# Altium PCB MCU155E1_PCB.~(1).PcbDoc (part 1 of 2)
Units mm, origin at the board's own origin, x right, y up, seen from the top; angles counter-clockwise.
Board outline 32 x 29 mm, 4 copper layers (Top Layer, Layer 1, Layer 2, Bottom Layer), stack 1.567 mm thick; 102 components, 61 nets, 283 pads, 120 vias.
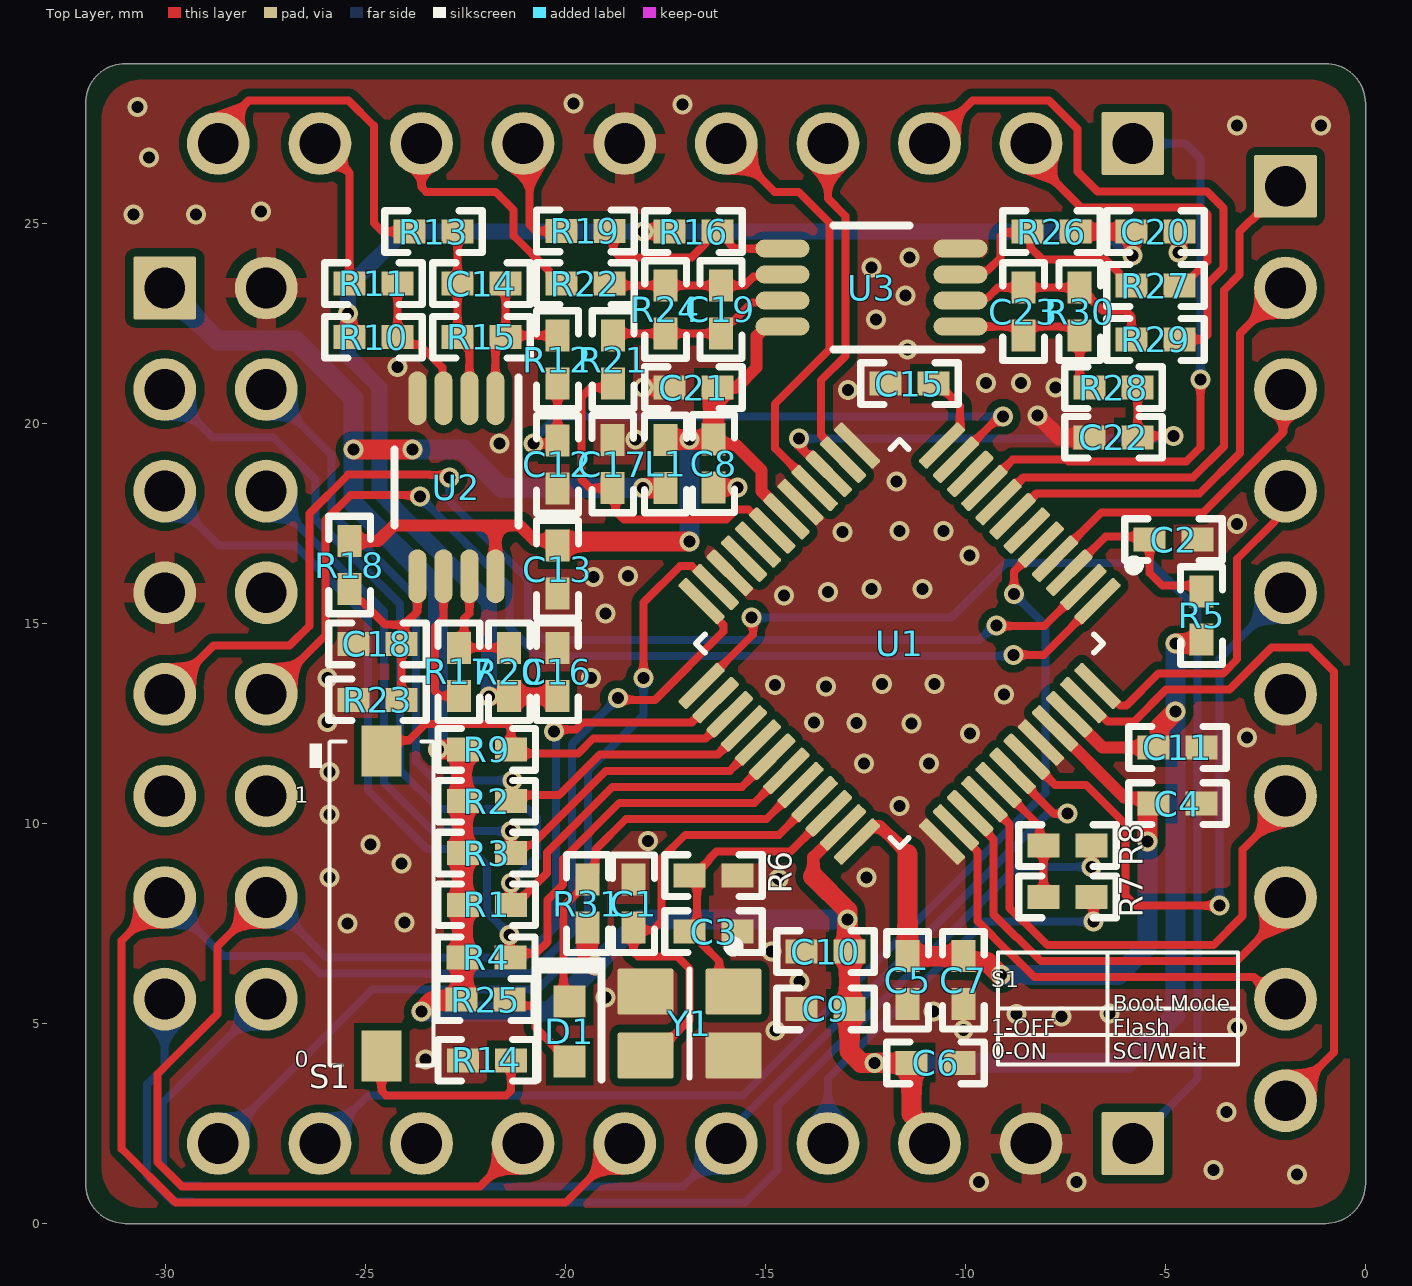
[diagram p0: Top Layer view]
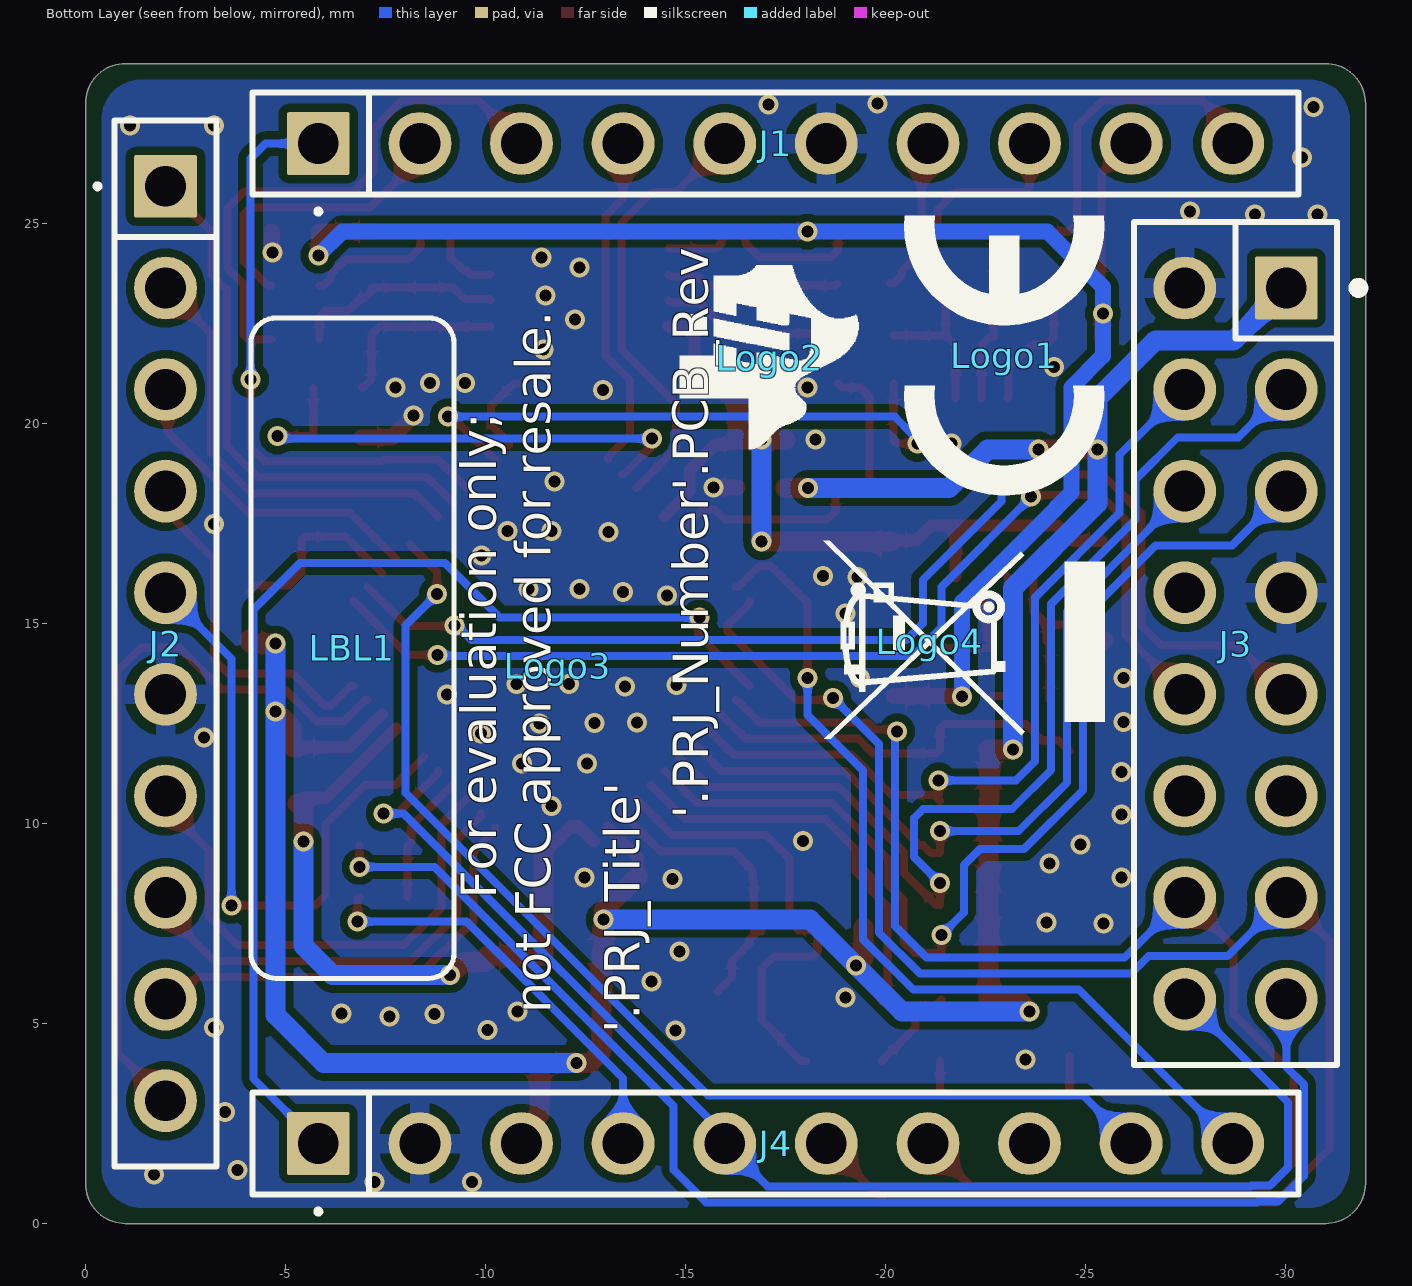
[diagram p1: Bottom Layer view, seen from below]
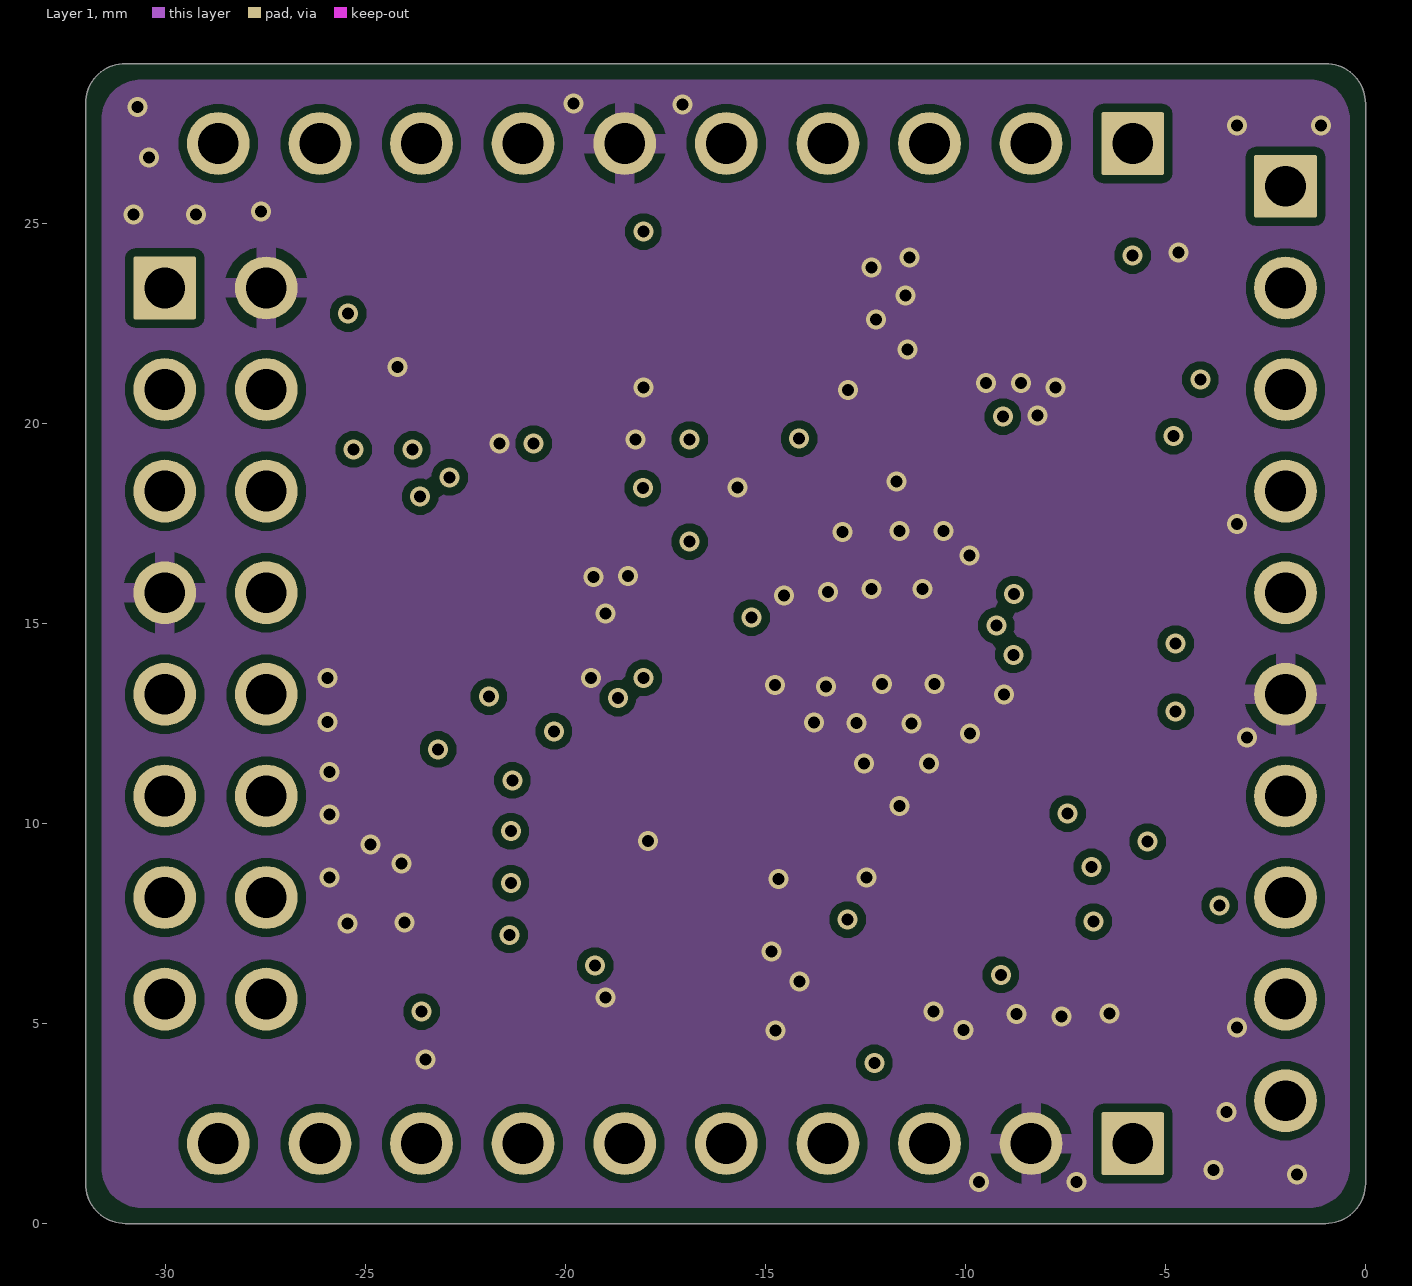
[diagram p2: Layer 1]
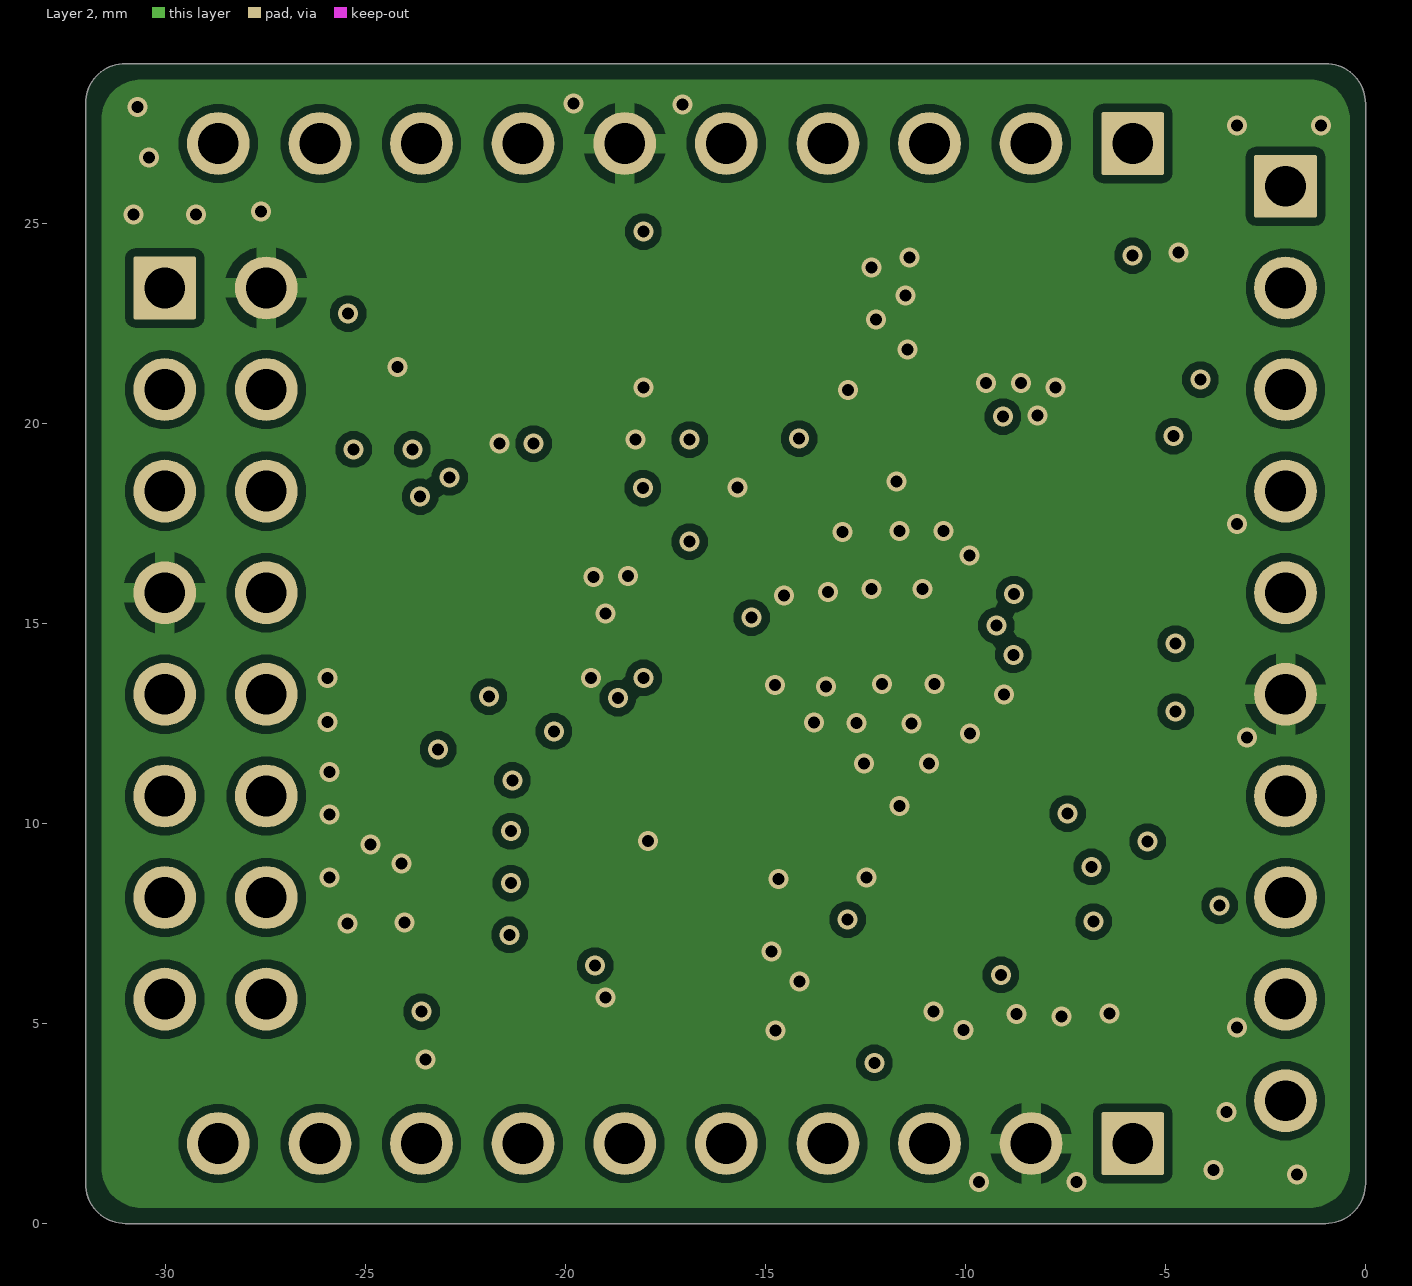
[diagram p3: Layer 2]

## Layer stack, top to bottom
Top Solder: solder mask 0.0102, Solder Resist, Dk 3.5
Top Layer: signal copper 0.035
Dielectric 1: prepreg 0.2184, PP-023, Dk 4.5
Layer 1: signal copper 0.035
Dielectric1: core 0.9906, Core-042, Dk 4.6
Layer 2: signal copper 0.035
Dielectric 2: prepreg 0.2184, PP-023, Dk 4.5
Bottom Layer: signal copper 0.035
Bottom Solder: solder mask 0.0102, Solder Resist, Dk 3.5

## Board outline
-32,1 -32,28 cw(c-31,28) -31,29 -1,29 cw(c-1,28) 0,28 0,1 cw(c-1,1) -1,0 -31,0 cw(c-31,1)

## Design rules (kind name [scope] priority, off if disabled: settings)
AcuteAngle [All] p1: minimum=4.50000000000000E+0001 checktracksonly=FALSE
AssemblyTestPointUsage [All] p1: valid=2
BoardOutlineClearance BoardOutlineClearance_MountingHoles [OnCopper and InComponentClass('Mounting Holes')] p1: gap=0 ignorepadtopadclearanceinfootprint=FALSE
BoardOutlineClearance BoardOutlineClearance_Poly [OnCopper and IsPoly] p2: gap=0 ignorepadtopadclearanceinfootprint=FALSE
BoardOutlineClearance [OnCopper and Not InComponentClass('Logo') and not InComponentClass('FiducialMark') and not InRegion(1000,500,4000,800) and not InPoly] p3: gap=0 ignorepadtopadclearanceinfootprint=FALSE
Clearance Clearance_1 [(InComponent('J1') or InComponent('J2') or InComponent('J3') or InComponent('J4') ) and not HasFootprint('fiducial10-20')] p1: gap=0.19 ignorepadtopadclearanceinfootprint=TRUE
Clearance PB+ToPB- [InNetClass('HV') vs InNetClass('LV_Signal')] p2: gap=3 ignorepadtopadclearanceinfootprint=TRUE
Clearance PB-ToACN [InNetClass('LV Signal') vs InNetClass('ACN')] p3: gap=3 ignorepadtopadclearanceinfootprint=TRUE
Clearance ACLToACN [InNetClass('ACL') vs InNetClass('ACN')] p4: gap=2 ignorepadtopadclearanceinfootprint=FALSE
Clearance ISOToAll [InNetClass('Isolation') vs not InNetClass('Isolation')   and (not  OnLayer('Keep-Out Layer'))] p5: gap=6 ignorepadtopadclearanceinfootprint=TRUE
Clearance PB-ToACL [InNetClass('LV Signal') vs InNetClass('ACL')] p6: gap=3 ignorepadtopadclearanceinfootprint=TRUE
Clearance PB+ToACL [InNetClass('V_BUS') vs InNetClass('ACL')] p7: gap=3 ignorepadtopadclearanceinfootprint=TRUE
Clearance PB+ToACN [InNetClass('V_BUS') vs InNetClass('ACN')] p8: gap=1.5 ignorepadtopadclearanceinfootprint=TRUE
Clearance SMTPadToTHHole [not IsVia and OnLayer('Multi-Layer') and not InComponent('J1') and not InComponent('J2') and not InComponent('J3') and not InComponent('J4') and not InComponent('J12') and PadIsPlated vs InSMTComponent and OnLayer('Bottom Layer') and not HasFootprint('TP_SM_1MM')] p9: gap=0.15 ignorepadtopadclearanceinfootprint=FALSE except(3: SMDPad-THPad)
Clearance [All vs not HasFootprint('fiducial10-20') or (InComponent('J1') or InComponent('J2') or InComponent('J3') or InComponent('J4') )] p10: gap=0.2 ignorepadtopadclearanceinfootprint=TRUE
ComponentClearance ComponentClearance_MountingHoles_FiducialMarks [InComponentClass('Mounting Holes') vs InComponentClass('FiducialMark')] p1: gap=1.27 collisioncheckmode=3 verticalgap=0.254 showdistances=FALSE
ComponentClearance ComponentClearance_Shunt [InComponentClass('Header') vs InComponentClass('Shunt')] p2: gap=0 collisioncheckmode=3 verticalgap=0 showdistances=FALSE
ComponentClearance ComponentClearance_Logo [InComponentClass('Logo')] p3: gap=0.762 collisioncheckmode=3 verticalgap=0.254 showdistances=FALSE
ComponentClearance ComponentClearance_ScrewToNut [(HasFootprint('NY PMS 440 0025 PH')) vs (HasFootprint('Keystone_1902C'))] p4: gap=0.127 collisioncheckmode=3 verticalgap=0.254 showdistances=FALSE
ComponentClearance ComponentClearance_MountingHoles [InComponentClass('Mounting Holes')] p5: gap=2.54 collisioncheckmode=3 verticalgap=2540 showdistances=FALSE
ComponentClearance ComponentClearance_SmallPassives [HasFootprint('0201*') or HasFootprint('0402*') or HasFootprint('0508') or HasFootprint('0603*') or HasFootprint('0612') or HasFootprint('0805*') or HasFootprint('0815*') or HasFootprint('0830*') or HasFootprint('1206*') or HasFootprint('1210*') or HasFootprint('1808*') or HasFootprint('1812*') or HasFootprint('1825*') or HasFootprint('2010*') or HasFootprint('2220*') or HasFootprint('2225*') or HasFootprint('2512*') or HasFootprint('2728*') or HasFootprint('3518*') vs HasFootprint('0201*') or HasFootprint('0402*') or HasFootprint('0508') or HasFootprint('0603*') or HasFootprint('0612') or HasFootprint('0805*') or HasFootprint('0815*') or HasFootprint('0830*') or HasFootprint('1206*') or HasFootprint('1210*') or HasFootprint('1808*') or HasFootprint('1812*') or HasFootprint('1825*') or HasFootprint('2010*') or HasFootprint('2220*') or HasFootprint('2225*') or HasFootprint('2512*') or HasFootprint('2728*') or HasFootprint('3518*')] p6: gap=0.38 collisioncheckmode=3 verticalgap=0.254 showdistances=FALSE
ComponentClearance ComponentClearance_THtoSMT [IsThruComponent vs IsSMTComponent] p7: gap=0.762 collisioncheckmode=3 verticalgap=0.762 showdistances=FALSE
ComponentClearance ComponentClearance_THtoTH [IsThruComponent vs IsThruComponent] p8: gap=0.508 collisioncheckmode=3 verticalgap=0.762 showdistances=FALSE
ComponentClearance [All] p9: gap=0.508 collisioncheckmode=3 verticalgap=0.254 showdistances=FALSE
DiffPairsRouting [All] p1: maxlimit=2.54 minlimit=0.254 mostfreqgap=0.254 toplayer_minwidth=0.381 toplayer_maxwidth=0.381 toplayer_prefwidth=0.381 midlayer1_minwidth=0.381 midlayer1_maxwidth=0.381 midlayer1_prefwidth=0.381 midlayer2_minwidth=0.381 midlayer2_maxwidth=0.381 midlayer2_prefwidth=0.381 bottomlayer_minwidth=0.381 bottomlayer_maxwidth=0.381 bottomlayer_prefwidth=0.381 maxuncoupledlength=25.4
FabricationTestPointUsage TestPointUsage [All] p1: valid=2 allowmultiple=FALSE
FabricationTestpoint Testpoint [All] p1: side=3 testpointundercomponent=TRUE minsize=1.016 maxsize=2.54 preferedsize=1.524 minholesize=0 maxholesize=1.016 preferedholesize=0.813 testpointgrid=0.025 allowsidetop=TRUE allowsidebottom=TRUE usegrid=TRUE gridtolerance=0
FanoutControl Fanout_LCC [IsLCC] p1: bgadir=Out bgaviamode=Centered fanoutstyle=Auto fanoutdirection=Alternating viagrid=0.025 // Fanout_LCC (Default Rule)
FanoutControl Fanout_BGA [IsBGA] p2: bgadir=Out bgaviamode=Centered fanoutstyle=Auto fanoutdirection=Alternating viagrid=0.025 // Fanout_BGA (Default Rule)
FanoutControl Fanout_Default [All] p4: bgadir=Out bgaviamode=Centered fanoutstyle=Auto fanoutdirection=Alternating viagrid=0.025 // Fanout_Default (Default Rule)
FanoutControl Fanout_Small [(CompPinCount < 5)] p5: bgadir=Out bgaviamode=Centered fanoutstyle=Auto fanoutdirection=OutThenIn viagrid=0.025 // Fanout_Small (Default Rule)
HoleSize [All] p1: absolutevalues=TRUE maxlimit=6.375 minlimit=0.2 maxpercent=80.000 minpercent=20.000
MinimumAnnularRing MinimumAnnularRing_ThermalPadVias [IsVia and InAnyComponent] p1: minimumring=0.15
MinimumAnnularRing [All] p2: minimumring=0.2
MinimumSolderMaskSliver MinimumSolderMaskSliver_Logo [InComponentClass('Logo') vs InComponentClass('Logo')] p1: minsoldermaskwidth=0.018
MinimumSolderMaskSliver [All] p2: minsoldermaskwidth=0.1
PlaneConnect [All] p1: planeconnectstyle=Direct reliefexpansion=0.254 reliefentries=4 reliefconductorwidth=0.254 reliefairgap=0.254
PolygonConnect "Thermal relief" [All vs InNet('GND') or innet('GND_ISO')  or innet('ubus')] p1: thpad.connectstyle=Relief thpad.reliefconductorwidth=0.5 thpad.reliefentries=4 thpad.polygonreliefangle="90 Angle" thpad.airgapwidth=0.254 smdpad.connectstyle=Direct smdpad.reliefconductorwidth=0.5 smdpad.reliefentries=4 smdpad.polygonreliefangle="90 Angle" smdpad.airgapwidth=0.254 via.connectstyle=Direct via.reliefconductorwidth=0.5 via.reliefentries=4 via.polygonreliefangle="90 Angle" via.airgapwidth=0.254
PolygonConnect [All] p2: connectstyle=Direct reliefconductorwidth=0.254 reliefentries=4 polygonreliefangle="90 Angle" airgapwidth=0.254
RoutingVias ThermalPadVias [IsVia and InAnyComponent] p1: holewidth=0.2 width=0.5 viastyle="Through Hole" minholewidth=0.2 minwidth=0.5 maxholewidth=0.33 maxwidth=0.6
RoutingVias [All] p2: holewidth=0.2 width=0.5 viastyle="Through Hole" minholewidth=0.2 minwidth=0.4 maxholewidth=1 maxwidth=1.4
SilkToBoardRegionClearance [Not ((IsComment or IsDesignator) And (Hide <> 'False')) and not InRegion(1000,500,4000,800)] p1:
SilkToSilkClearance SilkToSilkClearance_Pb-FreeLogo [(HasFootprint('Pb-Free_Overlay_Medium') OR HasFootprint('Pb-Free_Overlay_Small')) vs (HasFootprint('Pb-Free_Overlay_Medium') OR HasFootprint('Pb-Free_Overlay_Small'))] p1: silktosilkclearance=0
SilkToSilkClearance [All] p2: silktosilkclearance=0.1
SilkToSolderMaskClearance SilkToComponentPadClearance [(IsPad or IsFill or IsRegion) and InAnycomponent] p1: minsilkscreentomaskgap=0.127 clearancetoexposedcopper=TRUE
SilkToSolderMaskClearance "Silk to Solder Mask Opening" [All] p2: minsilkscreentomaskgap=0.1 clearancetoexposedcopper=FALSE
SolderMaskExpansion [All] p1: expansion=0.05 istentingtop=FALSE
UnRoutedNet [All] p1: checkbadconnections=TRUE
Width [All] p1: maxlimit=5 minlimit=0.2 preferedwidth=0.3 minimp=50.000000 maximp=50.000000 favimp=50.000000 checkconnectedcopper=TRUE
14 further rules are at their usual default settings.

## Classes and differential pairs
component class Logo: Logo2
component class Label: LBL1
component class TIEVM-MC-MODULE-F280013x: C1 C2 C3 C4 C5 C6 C7 C8 C9 C10 C11 C12 C13 C14 C15 C16 C17 C18 C19 C20 C21 C22 C23 D1 J1 J2 J3 J4 L1 LBL1 Logo1 Logo2 Logo3 Logo4 R1 R2 R3 R4 R5 R6 R7 R8 R9 R10 R11 R12 R13 R14 R15 R16 R17 R18 R19 R20 R21 R22 R23 R24 R25 R26 R27 R28 R29 R30 R31 S1 U1 U2 U3 Y1

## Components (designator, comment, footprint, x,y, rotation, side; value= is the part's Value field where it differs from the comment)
C1 "GRM1555C1H120JA01D" 0402 -18.3,7.998 r270 top value=12pF
C2 "GRM155R71C104KA88D" 0402 -4.8,17.1 r0 top value=0.1uF
C3 "GRM1555C1H120JA01D" 0402 -16.3,7.3 r0 top value=12pF
C4 "GRM155R71C104KA88D" 0402 -4.7,10.5 r180 top value=0.1uF
C5 "GRM155R71C104KA88D" 0402 -11.448,6.083 r90 top value=0.1uF
C6 "GRM155R61A106ME11" 0402 -10.75,4.015 r0 top value=10uF
C7 "GRM155R61A106ME11" 0402 -10.051,6.083 r90 top value=10uF
C8 "GRM155R61A106ME11" 0402 -16.3,19 r270 top value=10uF
C9 "GRM155R61A106ME11" 0402 -13.5,5.366 r180 top value=10uF
C10 "GRM155R71C104KA88D" 0402 -13.5,6.8 r180 top value=0.1uF
C11 "GRM155R71C104KA88D" 0402 -4.7,11.901 r0 top value=0.1uF
C12 "C1005C0G1H221F050BA" 0402 -20.2,18.977 r270 top value=220pF
C13 "GRM155R71C104KA88D" 0402 -20.2,16.353 r270 top value=0.1uF
C14 "GRM1555C1H101JA01D" 0402 -22.1,23.5 r0 top value=100pF
C15 "GRM155R61A225ME95" 0402 -11.4,21 r180 top value=2.2uF
C16 "GRM155R61C103KA01D" 0402 -20.201,13.793 r90 top value=0.01uF
C17 "C1005C0G1H221F050BA" 0402 -18.82,18.988 r90 top value=220pF
C18 "GRM155R71C104KA88D" 0402 -24.701,14.491 r180 top value=0.1uF
C19 "GRM1555C1H101JA01D" 0402 -16.113,22.852 r270 top value=100pF
C20 "GRM155R71C104KA88D" 0402 -5.25,24.8 r0 top value=0.1uF
C21 "GRM155R71C104KA88D" 0402 -16.8,20.9 r180 top value=0.1uF
C22 "C1005C0G1H221F050BA" 0402 -6.3,19.656 r180 top value=220pF
C23 "GRM1555C1H101JA01D" 0402 -8.548,22.8 r270 top value=100pF
D1 "LTST-C193KRKT-5A" LTST-C193_Red -19.9,4.8 r90 top value=Red
J1 "SSQ-110-03-T-S" FP-SSQ-110-03-T-S_CONN_RCPT10-MFG -17.25,27 r180 bottom
J2 "SSQ-110-03-T-S" FP-SSQ-110-03-T-S_CONN_RCPT10-MFG -2,14.5 r270 bottom locked
J3 "SSQ-108-03-T-D" FP-SSQ-108-03-T-D_HDR16-MFG -28.75,14.5 r270 bottom locked
J4 "SSQ-110-03-T-S" FP-SSQ-110-03-T-S_CONN_RCPT10-MFG -17.25,2 r180 bottom locked
L1 "782423100" 0402 -17.5,18.988 r90 top value="10 ohm"
LBL1 "THT-14-423-10" Label_650x200 -6.674,14.385 r270 bottom
Logo1 "CE Mark" CE_Mark_5mm -22.967,21.7 r90 bottom
Logo2 "Texas Instruments" TI_Symbol_Overlay_Small -17.1,21.65 r90 bottom
Logo3 "FCC disclaimer" FCC_disclaimer_stacked -11.8,13.95 r90 bottom
Logo4 "WEEE logo" WEEE_Minimum -21.1,14.55 r90 bottom
M44 "Comment" Arrow 343.55,113.9 r0 top
M45 "Comment" Arrow 386.55,113.9 r180 bottom
M46 "Comment" MARK 416.05,-5.6 r0 top
M47 "Comment" Toolinghole 401.05,-7.1 r0 top
M48 "Comment" "White oil-26X4" 322.05,111.9 r0 top
M49 "Comment" "Bad Mark" 386.05,-5.6 r0 top
M49 "Comment" MARK 411.05,-5.6 r0 top
M49_1 "Comment" "Bad Mark" 354.05,-5.6 r0 top
M49_2 "Comment" "Bad Mark" 322.05,-5.6 r0 top
M50 "Comment" MARK 266.05,-5.6 r0 top
M51 "Comment" MARK 266.05,112.4 r0 top
M52 "Comment" MARK 416.05,112.4 r0 top
M53 "Comment" Toolinghole 276.05,-7.1 r0 top
M54 "Comment" Toolinghole 276.05,113.9 r0 top
M55 "Comment" Toolinghole 406.05,113.9 r0 top
M56 "Comment" "Bad Mark" 381.05,-5.6 r0 top
M56_1 "Comment" "Bad Mark" 349.05,-5.6 r0 top
M56_2 "Comment" "Bad Mark" 317.05,-5.6 r0 top
M57 "Comment" "Bad Mark" 376.05,-5.6 r0 top
M57_1 "Comment" "Bad Mark" 344.05,-5.6 r0 top
M57_2 "Comment" "Bad Mark" 312.05,-5.6 r0 top
M57_2_1 "Comment" "Bad Mark" 302.05,-5.6 r0 top
M57_2_2 "Comment" "Bad Mark" 290.05,-5.6 r0 top
M58 "Comment" "Bad Mark" 371.05,-5.6 r0 top
M58_1 "Comment" "Bad Mark" 339.05,-5.6 r0 top
M58_2 "Comment" "Bad Mark" 307.05,-5.6 r0 top
M58_2_1 "Comment" "Bad Mark" 297.05,-5.6 r0 top
M59 "Comment" "Bad Mark" 366.05,-5.6 r0 top
M59_1 "Comment" "Bad Mark" 334.05,-5.6 r0 top
M60 "Comment" "Bad Mark" 361.05,-5.6 r0 top
M60_1 "Comment" "Bad Mark" 329.05,-5.6 r0 top
M61 "Comment" "Bad Mark" 393.05,-5.6 r0 top
R1 "ERJ-2RKF2401X" 0402 -21.965,7.967 r180 top value=2.40k
R2 "RC0402FR-0710KL" 0402 -21.965,10.557 r180 top value=10.0k
R3 "RC0402FR-0710KL" 0402 -21.965,9.262 r180 top value=10.0k
R4 "RC0402FR-0710KL" 0402 -21.981,6.647 r180 top value=10.0k
R5 "RC0402FR-0710KL" 0402 -4.1,15.2 r270 top value=10.0k
R6 "RG1005P-104-B-T5" 0402 -16.3,8.698 r180 top value=100k
R7 "RC0402JR-070RL" 0402 -7.45,8.165 r180 top value=0
R8 "RC0402JR-070RL" 0402 -7.45,9.45 r180 top value=0
R9 "CMP-0026949-3" 0402 -21.965,11.852 r180 top value=56k
R10 "RC0402FR-0710KL" 0402 -24.8,22.158 r180 top value=10.0k
R11 "ERJ-2RKF2401X" 0402 -24.8,23.5 r0 top value=2.40k
R12 "RC0402FR-07100RL" 0402 -20.2,21.6 r270 top value=100
R13 "ERJ-2RKF2401X" 0402 -23.3,24.8 r0 top value=2.40k
R14 "CMP-0026890-5" 0402 -21.965,4.082 r180 top value=2.2k
R15 "RC0402FR-0710KL" 0402 -22.1,22.158 r0 top value=10.0k
R16 "RC0402FR-0710KL" 0402 -16.8,24.8 r180 top value=10.0k
R17 "RC0402FR-0710KL" 0402 -22.664,13.793 r270 top value=10.0k
R18 "RC0402FR-0710KL" 0402 -25.399,16.463 r90 top value=10.0k
R19 "ERJ-2RKF2401X" 0402 -19.501,24.814 r0 top value=2.40k
R20 "RC0402FR-07100RL" 0402 -21.407,13.793 r270 top value=100
R21 "RC0402FR-07100RL" 0402 -18.811,21.6 r270 top value=100
R22 "ERJ-2RKF2401X" 0402 -19.501,23.5 r0 top value=2.40k
R23 "RC0402FR-0710KL" 0402 -24.7,13.094 r0 top value=10.0k
R24 "RC0402FR-0710KL" 0402 -17.498,22.852 r270 top value=10.0k
R25 "RC0402FR-071KL" 0402 -22,5.6 r0 top value=1.00k
R26 "RC0402FR-0710KL" 0402 -7.85,24.8 r0 top value=10.0k
R27 "ERJ-2RKF2401X" 0402 -5.25,23.451 r180 top value=2.40k
R28 "RC0402FR-07100RL" 0402 -6.3,20.9 r0 top value=100
R29 "ERJ-2RKF2401X" 0402 -5.25,22.101 r180 top value=2.40k
R30 "RC0402FR-0710KL" 0402 -7.146,22.8 r270 top value=10.0k
R31 "CMP-0026949-3" 0402 -19.45,8 r270 top value=56k
S1 "CHS-01TB" SW_CHS-01TB -24.6,8 r0 top
U1 "F2800137PT" PT0048A-MFG -11.65,14.5 r225 top locked
U2 "TLV9062IDGKR" DGK0008A_N -22.727,18.406 r270 top
U3 "TLV9062IDGKR" DGK0008A_N -12.35,23.4 r180 top
Y1 "830108207209" FP-830108207209_SMT_CRYSTAL_3MM2_2MM5-MFG -16.9,5 r180 top

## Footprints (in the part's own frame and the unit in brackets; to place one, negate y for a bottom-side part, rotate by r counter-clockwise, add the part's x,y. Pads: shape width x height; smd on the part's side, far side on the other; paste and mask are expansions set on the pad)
0402 [mm] "0402 from SM-752 data"
  rect 0.8x0.6 smd: 1(-0.6,0) 2(0.6,0)
  silkscreen extent -1.22,-0.52 1.22,0.52, body extent -0.55,-0.3 0.55,0.3, height 0.6
Arrow [mm] "·½Ïò¼ýÍ·"
  silkscreen extent 0,-2 43,2
"Bad Mark" [mm]
  round 2 on Bottom Solder: 2(0,0)
  round 2 on Top Solder: 2(0,0)
  Top Layer pour cut-out: -1.051,0 -0.971,-0.402 -0.743,-0.743 -0.402,-0.971 0,-1.051 0,-1.051 0.402,-0.971 0.743,-0.743 0.971,-0.402 1.051,0 1.051,0 0.971,0.402 0.743,0.743 0.402,0.971 0,1.051 0,1.051 -0.402,0.971 -0.743,0.743 -0.971,0.402 -1.051,0
  Top Layer region: -0.5,-0.25 -0.5,0.25 0.5,0.25 0.5,-0.25
  Top Layer region: -0.25,0.5 0.25,0.5 0.25,-0.5 -0.25,-0.5
  Bottom Layer pour cut-out: 1.051,0 0.971,-0.402 0.743,-0.743 0.402,-0.971 0,-1.051 0,-1.051 -0.402,-0.971 -0.743,-0.743 -0.971,-0.402 -1.051,0 -1.051,0 -0.971,0.402 -0.743,0.743 -0.402,0.971 0,1.051 0,1.051 0.402,0.971 0.743,0.743 0.971,0.402 1.051,0
  Bottom Layer region: 0.25,0.5 -0.25,0.5 -0.25,-0.5 0.25,-0.5
  Bottom Layer region: 0.5,-0.25 0.5,0.25 -0.5,0.25 -0.5,-0.25
CE_Mark_5mm [mm] "Minimum text height for CE Mark"
  silkscreen extent -3.5,-2.5 3.5,2.5
DGK0008A_N [mm] "TSOP, 8-Leads, Body 3x3mm, Pitch 0.65mm, IPC Medium Density"
  oval 1.35x0.45 smd: 1(-2.225,0.975) 2(-2.225,0.325) 3(-2.225,-0.325) 4(-2.225,-0.975) 5(2.225,-0.975) 6(2.225,-0.325) 7(2.225,0.325) 8(2.225,0.975)
  silkscreen extent -2.75,-1.55 0.95,1.55, body extent -2.45,-1.5 2.45,1.5, height 0.96
FCC_disclaimer_stacked [mm]
FP-830108207209_SMT_CRYSTAL_3MM2_2MM5-MFG [mm]
  rrect9% 1.4x1.15 smd paste+0 mask+0: 1(-1.1,-0.8) 2(1.1,-0.8) 3(1.1,0.8) 4(-1.1,0.8)
  silkscreen extent -1.23,-2.05 0,1.35, body extent -1.9,-1.47 1.9,1.48, height 0.25
FP-SSQ-108-03-T-D_HDR16-MFG [mm]
  rrect6% 1.57x1.57 hole 1.02 paste+0 mask+0: 1(-8.89,1.27)
  round 1.57 hole 1.02 paste+0 mask+0: 2(-8.89,-1.27) 3(-6.35,1.27) 4(-6.35,-1.27) 5(-3.81,1.27) 6(-3.81,-1.27) 7(-1.27,1.27) 8(-1.27,-1.27) 9(1.27,1.27) 10(1.27,-1.27) 11(3.81,1.27) 12(3.81,-1.27) 13(6.35,1.27) 14(6.35,-1.27) 15(8.89,1.27) 16(8.89,-1.27)
  silkscreen extent -10.54,-2.54 10.54,3.19, body extent -10.42,-2.48 10.42,2.48, height 8.64
FP-SSQ-110-03-T-S_CONN_RCPT10-MFG [mm]
  rrect6% 1.57x1.57 hole 1.02 paste+0 mask+0: 1(-11.43,0)
  round 1.57 hole 1.02 paste+0 mask+0: 2(-8.89,0) 3(-6.35,0) 4(-3.81,0) 5(-1.27,0) 6(1.27,0) 7(3.81,0) 8(6.35,0) 9(8.89,0) 10(11.43,0)
  silkscreen extent -13.08,-1.76 13.08,1.27, body extent -12.95,-1.21 12.95,1.21, height 8.64
Label_650x200 [mil] "Thermal Transfer Label"
  round 1 on Mech14: 0(0,0)
  silkscreen extent -325,-100 325,100, body extent -325,-100 325,100, height 1
LTST-C193_Red [mm] "SMD, 2-Leads, Body1.6x0.8mm"
  rect 0.8x0.8 smd: 1(-0.75,0) 2(0.75,0)
  silkscreen extent -1.2,-0.9 1.85,0.9, body extent -0.85,-0.45 0.85,0.45, height 0.45
MARK [mm]
  round 1 smd mask+0.5: 1(0,0)
  round 1 smd far side mask+0.5: 2(0,0)
  Top Layer pour cut-out: -1.5,0 -1.386,-0.574 -1.061,-1.061 -0.574,-1.386 0,-1.5 0,-1.5 0.574,-1.386 1.061,-1.061 1.386,-0.574 1.5,0 1.5,0 1.386,0.574 1.061,1.061 0.574,1.386 0,1.5 0,1.5 -0.574,1.386 -1.061,1.061 -1.386,0.574 -1.5,0
  Bottom Layer pour cut-out: -1.5,0 -1.386,-0.574 -1.061,-1.061 -0.574,-1.386 0,-1.5 0,-1.5 0.574,-1.386 1.061,-1.061 1.386,-0.574 1.5,0 1.5,0 1.386,0.574 1.061,1.061 0.574,1.386 0,1.5 0,1.5 -0.574,1.386 -1.061,1.061 -1.386,0.574 -1.5,0
PT0048A-MFG [mm]
  rrect33% 1.4x0.3 smd paste-1000 mask+0: 1(-4.25,2.75) 2(-4.25,2.25) 3(-4.25,1.75) 4(-4.25,1.25) 5(-4.25,0.75) 6(-4.25,0.25) 7(-4.25,-0.25) 8(-4.25,-0.75) 9(-4.25,-1.25) 10(-4.25,-1.75) 11(-4.25,-2.25) 12(-4.25,-2.75) 25(4.25,-2.75) 26(4.25,-2.25) 27(4.25,-1.75) 28(4.25,-1.25) 29(4.25,-0.75) 30(4.25,-0.25) 31(4.25,0.25) 32(4.25,0.75) 33(4.25,1.25) 34(4.25,1.75) 35(4.25,2.25) 36(4.25,2.75)
  rrect33% 0.3x1.4 smd paste-1000 mask+0: 13(-2.75,-4.25) 14(-2.25,-4.25) 15(-1.75,-4.25) 16(-1.25,-4.25) 17(-0.75,-4.25) 18(-0.25,-4.25) 19(0.25,-4.25) 20(0.75,-4.25) 21(1.25,-4.25) 22(1.75,-4.25) 23(2.25,-4.25) 24(2.75,-4.25) 37(2.75,4.25) 38(2.25,4.25) 39(1.75,4.25) 40(1.25,4.25) 41(0.75,4.25) 42(0.25,4.25) 43(-0.25,4.25) 44(-0.75,4.25) 45(-1.25,4.25) 46(-1.75,4.25) 47(-2.25,4.25) 48(-2.75,4.25)
  silkscreen extent -5.65,-3.6 3.6,3.6, body extent -5.05,-5.05 5.05,5.05, height 0.25
SW_CHS-01TB [mm] "CHS Recommended footprint"
  rect 1x1.27 smd: 1(0,3.81) 2(0,-3.81)
  silkscreen extent -1.8,-4.05 1.3,4.05, body extent -1.25,-4 1.25,4, height 2.51
TI_Symbol_Overlay_Small [mm]
  silkscreen extent -2.3,-2.23 2.3,2.24
Toolinghole [mm]
  round 2 hole 2 unplated: 1(0,0)
  silkscreen extent -1.41,-1.41 1.41,1.41
WEEE_Minimum [mm] "WEEElie bin"
  silkscreen extent -2.42,-4.38 2.52,2.65
"White oil-26X4" [mm] "¶þÎ¬Âë°×ÓÍ¿ò"
  silkscreen extent -26,0 0,4

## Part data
C1 C3: library part CMP-0006415-2, "CAP, CERM, 12 pF, 50 V, +/- 5%, C0G/NP0, 0402", Cap_Case=0402, Manufacturer=MuRata, Supplier Part Number 1=14T3292, TempCo=C0G/NP0, Tolerance_%=5%, Value1=Unknown, Value2=50V, ValueDisplayed=12pF
C2 C4 C5 C10 C11 C13 C18 C20 C21: library part CMP-0006641-2, "CAP, CERM, 0.1 uF, 16 V, +/- 10%, X7R, 0402", Cap_Case=0402, Manufacturer=MuRata, Supplier Part Number 1=490-3261-1-ND, TempCo=X7R, Tolerance_%=10%, Value1=Unknown, Value2=16V, ValueDisplayed=0.1uF
C6 C7 C8 C9: library part CMP-0006564-1, "CAP, CERM, 10 uF, 10 V, +/- 20%, X5R, 0402", Cap_Case=0402, Manufacturer=MuRata, TempCo=X5R, Tolerance_%=20%, Value1=Unknown, Value2=10V, ValueDisplayed=10uF
C12 C17 C22: library part CMP-0006249-2, "CAP, CERM, 220 pF, 50 V, +/- 1%, C0G/NP0, 0402", Cap_Case=0402, Manufacturer=TDK, Supplier Part Number 1=445-7015-1-ND, TempCo=C0G/NP0, Tolerance_%=1%, Value1=Unknown, Value2=50V, ValueDisplayed=220pF
C14 C19 C23: library part CMP-0006410-2, "CAP, CERM, 100 pF, 50 V, +/- 5%, C0G/NP0, 0402", Cap_Case=0402, Manufacturer=MuRata, Supplier Part Number 1=81-GRM1555C1H101JA1D, TempCo=C0G/NP0, Tolerance_%=5%, Value1=Unknown, Value2=50V, ValueDisplayed=100pF
C15: library part CMP-0006571-2, "CAP, CERM, 2.2 uF, 10 V, +/- 20%, X5R, 0402", Cap_Case=0402, Manufacturer=MuRata, Supplier Part Number 1=490-10452-1-ND, TempCo=X5R, Tolerance_%=20%, Value1=Unknown, Value2=10V, ValueDisplayed=2.2uF
C16: library part CMP-0006590-2, "CAP, CERM, 0.01 uF, 16 V, +/- 10%, X5R, 0402", Cap_Case=0402, Manufacturer=MuRata, Supplier Part Number 1=GRM155R61C103KA01D-ND, TempCo=X5R, Tolerance_%=10%, Value1=Unknown, Value2=16V, ValueDisplayed=0.01uF
D1: library part CMP-0079922-3, "LED, Red, SMD", Color=Red, Manufacturer=Lite-On, Value1=W, Value2=2V
J1 J2 J4: library part CMP-0123041-2, "Conn Socket Strip SKT 10 POS 2.54mm Solder ST Top Entry Thru-Hole Bulk", Current_A=6.3A, Digikey Part Number=SAM1206-10-ND, Manufacturer=Samtec, Mouser Part Number=200-SSQ11003TS, Octopart Part Number=b25e7b5014d46d99, Operating Temperature Range="-55°C to +105°C", Voltage_V=655V
J3: library part CMP-0123022-2, "16 Position Receptacle Connector 0.100\" (2.54mm) Through Hole Tin", Current_A=6.3A, Digikey Part Number=SAM1204-08-ND, Manufacturer=Samtec, Mouser Part Number=200-SSQ10803TD, Octopart Part Number=1608df06b0e9c9cf, Operating Temperature Range="-55°C to +105°C", Voltage_V=655V
L1: library part CMP-0003274-1, "Ferrite Bead, 10 ohm @ 100 MHz, 1.5 A, 0402", Manufacturer="Wurth Elektronik", Supplier Part Number 1=732-6691-1-ND, Value1="0.03 ohm", Value2=1.5A, ValueDisplayed="10 ohm"
LBL1: library part CMP-0003625-1, "Thermal Transfer Printable Labels, 0.650\" W x 0.200\" H - 10,000 per roll", Manufacturer=Brady, Supplier Part Number 1=97C5133
Logo1: library part CMP-0074844-1
Logo2: library part CMP-0074838-1, "Texas Instrument Corporate Signature"
Logo3: library part CMP-0074847-1, "FCC_disclaimer"
Logo4: library part CMP-0074769-1
R1 R11 R13 R19 R22 R27 R29: library part CMP-0026685-1, "RES, 2.40 k, 1%, 0.1 W, AEC-Q200 Grade 0, 0402", Manufacturer=Panasonic, Power_W=100mW, Supplier Part Number 1=P2.40KLCT-ND, TempCo="100 ppm/C", Tolerance_%=1%, Value2=0.1W, Value_Code=2k40, ValueDisplayed=2.40k
R2 R3 R4 R5 R10 R15 R16 R17 R18 R23 R24 R26 R30: library part CMP-0078669-1, "RES, 10.0 k, 1%, 0.063 W, 0402", Manufacturer="Yageo America", Power_W=63mW, Supplier Part Number 1=311-10.0KLRCT-ND, TempCo="100 ppm/C", Tolerance_%=1%, Value2=0.063W, Value_Code=10k0, ValueDisplayed=10.0k
R6: library part CMP-0026815-1, "RES, 100 k, 0.1%, 0.063 W, 0402", Manufacturer="Susumu Co Ltd", Power_W=63mW, Supplier Part Number 1=RG10P100KBCT-ND, TempCo="25 ppm/C", Tolerance_%=0.1%, Value2=0.063W, Value_Code=100k
R7 R8: library part CMP-0027004-2, "RES, 0, 5%, 0.063 W, 0402", Manufacturer="Yageo America", Power_W=63mW, Supplier Part Number 1=311-0.0JRCT-ND, TempCo="200 ppm/C", Tolerance_%=5%, Value2=0.063W, Value_Code=0000, ValueDisplayed=0
R9 R31: "RES, 56 k, 5%, 0.063 W, AEC-Q200 Grade 0, 0402", Manufacturer=Vishay-Dale, PartNumber=CRCW040256K0JNED, Power_W=63mW, Supplier Part Number 1=541-56KJCT-ND, TempCo="200 ppm/C", Tolerance_%=5%, Value2=0.063W, Value_Code=56k0, ValueDisplayed=56k
R12 R20 R21 R28: library part CMP-0026722-1, "RES, 100, 1%, 0.063 W, 0402", Manufacturer="Yageo America", Power_W=63mW, Supplier Part Number 1=311-100LRCT-ND, TempCo="100 ppm/C", Tolerance_%=1%, Value2=0.063W, Value_Code=100R, ValueDisplayed=100
R14: "RES, 2.2 k, 5%, 0.063 W, AEC-Q200 Grade 0, 0402", Manufacturer=Vishay-Dale, PartNumber=CRCW04022K20JNED, Power_W=63mW, Supplier Part Number 1=541-2.2KJCT-ND, TempCo="200 ppm/C", Tolerance_%=5%, Value2=0.063W, Value_Code=2k20, ValueDisplayed=2.2k
R25: library part CMP-0026725-1, "RES, 1.00 k, 1%, 0.0625 W, 0402", Manufacturer="Yageo America", Power_W=62.5mW, Supplier Part Number 1=311-1.00KLRCT-ND, TempCo="100 ppm/C", Tolerance_%=1%, Value2=0.0625W, Value_Code=1k00, ValueDisplayed=1.00k
S1: library part CMP-0002163-2, "Switch, Slide, SPST, Top Slide, SMT", CurrentRating_mA=100A, Manufacturer="Copal Electronics", Supplier Part Number 1=563-1004-1-ND
U1: library part CMP-0096487-1, "Real-Time Microcontrollers", Frequency_Fixed=120MHz, Manufacturer="Texas Instruments", Max Supply Voltage=3.63V, Min Supply Voltage=2.8V, Operating Temperature Range="-40°C to +125°C"
U2 U3: library part CMP-0084063-1, "10-MHz, Low-Noise, RRIO, CMOS Operational Amplifier for Cost-Sensitive Systems, DGK0008A (VSSOP-8)", Alternate Manufacturer="Texas Instruments", Alternate PartNumber=TLV9062IDGKT, Operating Temperature Range="-40 to 125 C", Rating=Catalog
Y1: library part CMP-0093781-1, "20 MHz ±10ppm Crystal 8pF 50 Ohms 4-SMD, No Lead", Digikey Part Number=1923-830108207209CT-ND, Frequency Stability=20ppm, Frequency Tolerance=10ppm, Frequency_Fixed=20MHz, Load Capacitance=8pF, Manufacturer="Wurth Electronics", Mouser Part Number=710-830108207209, Operating Temperature Range="-40°C to +85°C"

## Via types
v1: diameter 0.5, hole 0.3, Top Layer to Bottom Layer, tented both sides, 120 vias

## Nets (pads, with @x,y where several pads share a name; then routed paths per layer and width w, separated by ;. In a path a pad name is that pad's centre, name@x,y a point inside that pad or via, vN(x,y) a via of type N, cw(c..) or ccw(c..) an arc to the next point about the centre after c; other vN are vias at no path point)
3.3V: C6.1 C9.1 C10.1 C11.1 J3.1 J4.3 L1.1 R1.2 R2.2 R3.2 R4.2 R5.2 R9.2 R25.1 R31.2 U1.35 U1.46 | length 76.2
  Top Layer w0.3: -13.807,8.68 -13.807,9.161 U1.35@-13.064,9.904 ; U1.46@-7.407,12.732 -6.577,11.901 C11.1@-5.3,11.901
  Top Layer w0.5: v1(-25.3,19.352) v1(-23.826,19.352) ; v1(-23.6,5.3) -23.33,5.57 -22.611,5.57 -22.581,5.6 -22.581,10.557 -22.6,10.577 -22.6,11.817 R9.2@-22.565,11.852 v1(-23.184,11.852) ; R31.2@-19.45,7.4 -19.45,6.637 v1(-19.263,6.45) ; v1(-18.063,18.388) L1.1@-17.5,18.388 ; -13.807,8.68 -12.95,7.824 -12.95,6.85 C10.1@-12.9,6.8 C9.1@-12.9,5.366 -12.9,4.308 -12.607,4.015 v1(-12.279,4.015) C6.1@-11.35,4.015 -11.35,2.734 -10.9,2.284 J4.3@-10.9,2 ; C11.1@-5.3,11.901 -5.2,11.901 -5.15,11.951 -5.15,12.407 -4.757,12.8 v1(-4.75,12.8) ; v1(-4.75,14.501) -4.15,14.501 -4.1,14.551 R5.2@-4.1,14.6
  Bottom Layer w0.5: J3.1@-30.02,23.39 -28.705,22.075 -26.744,22.075 -25.3,20.631 v1(-25.3,19.352) -25.3,18 -23.184,15.884 v1(-23.184,11.852) ; v1(-23.826,19.352) -22.556,19.352 -21.592,18.388 v1(-18.063,18.388) ; v1(-23.6,5.3) -20.413,5.3 -18.113,7.6 v1(-12.95,7.6) ; v1(-12.279,4.015) -5.951,4.015 -4.75,5.217 v1(-4.75,14.501)
A1.65V: C16.1 C20.1 R10.2 R16.2 R20.2 R26.2 | length 37.1
  Top Layer w0.4: v1(-25.435,22.75) -25.417,22.732 -25.417,22.175 R10.2@-25.4,22.158 ; v1(-21.914,13.175) -21.905,13.184 -21.416,13.184 R20.2@-21.407,13.193 C16.1@-20.201,13.193 ; v1(-18.051,24.8) R16.2@-17.4,24.8 ; R26.2@-7.25,24.8 C20.1@-5.85,24.8 -5.835,24.785 -5.835,24.216 v1(-5.82,24.201)
  Bottom Layer w0.4: v1(-21.914,13.175) -21.914,15.533 -24.293,17.912 -24.293,17.924 -24.65,18.281 -24.65,20.906 -25.435,21.691 v1(-25.435,22.75) -25.435,23.415 -24.05,24.8 v1(-18.051,24.8) -6.419,24.8 v1(-5.82,24.201)
A3.3V: C8.1 C13.1 C21.1 L1.2 R18.2 U1.18 U2.8 U3.8 | length 20.9
  Top Layer w0.3: R18.2@-25.399,17.063 -24.687,17.063 -24.298,17.451 -23.027,17.451 -23.022,17.456 -21.752,17.456 ; U2.8@-21.752,16.181 -21.752,17.456 ; C13.1@-20.15,17.046 -20.162,17.034 -20.21,17.082 -20.774,17.082 -21.149,17.456 -21.752,17.456 ; C8.1@-16.3,19.6 -16.177,19.477 -15.75,19.477 -15.1,18.827 -15.1,18.304 U1.18@-14.478,17.682 ; C21.1@-16.2,20.9 -15.726,20.9 -15.221,21.405 -15.221,22.189 -14.984,22.425 U3.8@-14.575,22.425
  Top Layer w0.5: C13.1@-20.15,17.046 v1(-16.9,17.046) ; L1.2@-17.5,19.588 -17.488,19.6 v1(-16.9,19.6) C8.1@-16.3,19.6 -16.3,20.85 -16.25,20.9 C21.1@-16.2,20.9
  Bottom Layer w0.5: v1(-16.9,17.046) v1(-16.9,19.6)
BOOT_MODE: R9.1 S1.1 U1.27 | length 10
  Top Layer w0.2: S1.1@-24.6,11.81 -24.333,12.077 -23.917,12.077 -23.502,12.493 -21.482,12.493 -21.365,12.376 R9.1@-21.365,11.852 -21.266,11.753 -19.684,11.753 -19.306,12.131 -16.494,12.131 U1.27@-15.893,12.732
GND: C1.1 C2.2 C3.2 C4.1 C5.1 C6.2 C7.1 C8.2 C9.2 C10.2 C11.2 C12.2 C13.2 C15.2 C16.2 C17.2 C18.2 C20.2 C21.2 C22.2 J1.6 J2.6 J3.2 J3.7 J4.2 R6.1 R14.2 R23.1 U1.13 U1.17 U1.22 U1.37 U1.44 U2.4 U3.4 Y1.2 Y1.4 | length 3.6
  Top Layer w0.4: C18.2@-25.501,14.591 -25.401,14.491 C18.2@-25.301,14.491 ; v1(-18.05,20.9) C21.2@-17.4,20.9 ; C8.2@-16.3,18.4 -16.297,18.403 -15.703,18.403 v1(-15.7,18.405) ; v1(-8.2,20.2) -7.656,19.656 C22.2@-6.9,19.656 ; v1(-4.676,24.279) -4.663,24.292 -4.663,24.787 C20.2@-4.65,24.8
  other v1: -9.661,1.041 -7.231,1.041 -1.714,1.225 -3.8,1.343 -3.481,2.794 -23.5,4.1 -14.75,4.83 -10.051,4.833 -3.207,4.9 -7.599,5.179 -8.722,5.237 -6.4,5.256 -10.8,5.3 -19,5.65 -14.15,6.05 -14.85,6.8 -25.45,7.5 -24.024,7.52 -14.67,8.61 -25.9,8.651 -12.479,8.651 -24.1,9 -24.879,9.48 -17.943,9.558 -25.9,10.232 -11.649,10.438 -25.9,11.283 -12.531,11.502 -10.912,11.495 -2.959,12.149 -9.887,12.254 -12.729,12.517 -11.355,12.5 -25.95,12.544 -13.788,12.531 -9.038,13.226 -13.488,13.43 -14.768,13.465 -12.088,13.493 -10.77,13.493 -19.361,13.64 -25.95,13.644 -19,15.256 -14.533,15.705 -13.434,15.79 -12.35,15.86 -11.076,15.86 -19.294,16.163 -18.437,16.187 -9.9,16.703 -13.08,17.293 -11.649,17.312 -10.551,17.312 -3.207,17.491 -11.722,18.551 -21.65,19.5 -18.25,19.6 -12.932,20.843 -7.75,20.9 -9.493,21.01 -8.613,21.01 -24.206,21.408 -11.45,21.85 -12.233,22.606 -11.499,23.202 -12.35,23.9 -11.4,24.15 -30.8,25.224 -29.24,25.224 -27.608,25.3 -30.417,26.646 -3.207,27.454 -1.108,27.454 -30.698,27.909 -17.077,27.975 -19.801,27.998
IPM_FAULT: J4.1 U1.25 | length 28.5
  Top Layer w0.2: U1.25@-16.6,13.439 -15.308,14.731 -15.308,15.108 v1(-15.35,15.15)
  Bottom Layer w0.2: v1(-15.35,15.15) -10.35,15.15 -8.985,16.515 -5.365,16.515 -4.2,15.35 -4.2,3.62 J4.1@-5.82,2
IU_AD: C12.1 R12.2 U1.11 | length 15.7
  Top Layer w0.2: v1(-20.8,19.5) -20.277,19.5 C12.1@-20.2,19.577 R12.2@-20.2,21 ; U1.11@-10.236,19.096 -9.218,20.114 -9.12,20.114 v1(-9.063,20.171)
  Bottom Layer w0.2: v1(-20.8,19.5) -20.8,19.581 -20.663,19.718 -20.663,19.741 -20.232,20.171 v1(-9.063,20.171)
IU_N: J1.10 R13.1 | length 8.2
  Top Layer w0.2: J1.10@-28.68,27 -28.68,27.32 -27.925,28.075 -25.423,28.075 -24.793,27.445 -24.793,25.014 -24.579,24.8 R13.1@-23.9,24.8
IU_P: J1.9 R11.1 | length 3.8
  Top Layer w0.2: J1.9@-26.14,27 -25.4,26.26 R11.1@-25.4,23.5
IV_AD: C17.1 R21.2 U1.19 | length 8.7
  Top Layer w0.2: R21.2@-18.811,21 -18.911,20.9 -19.361,20.9 -19.6,20.661 -19.6,18.599 -19.39,18.388 C17.1@-18.82,18.388 -18.747,18.316 -18.747,17.806 -18.537,17.596 -15.979,17.596 -15.719,17.855 -15.43,17.855 U1.19@-14.903,17.328
IV_N: J1.8 R22.1 | length 6
  Top Layer w0.2: J1.8@-23.6,27 -23.6,25.911 -23.483,25.794 -21.746,25.794 -21.295,25.342 -21.295,24.693 -20.401,23.8 -20.401,23.7 -20.201,23.5 R22.1@-20.101,23.5
IV_P: J1.7 R19.1 | length 3
  Top Layer w0.2: J1.7@-21.06,27 -20.895,26.835 -20.895,24.958 -20.751,24.814 R19.1@-20.101,24.814
IW_AD: C22.1 R28.2 U1.15 | length 12.8
  Top Layer w0.2: v1(-14.16,19.621) -14.103,19.564 -14.103,19.38 -13.466,18.743 U1.15@-13.418,18.743 ; R28.2@-5.7,20.9 C22.1@-5.7,19.656 -5.671,19.685 v1(-4.8,19.685)
  Bottom Layer w0.2: v1(-14.16,19.621) -4.945,19.621 -4.881,19.685 v1(-4.8,19.685)
IW_N: J1.3 R29.1 | length 13.6
  Top Layer w0.2: J1.3@-10.9,27 -9.825,28.075 -7.915,28.075 -7.2,27.36 -7.2,26.3 -6.7,25.8 -3.96,25.8 -3.55,25.39 -3.55,23.891 -3.95,23.491 -3.95,22.219 -4.067,22.101 R29.1@-4.65,22.101
IW_P: J1.2 R27.1 | length 7.5
  Top Layer w0.2: J1.2@-8.36,27 -8.36,26.646 -7.114,25.4 -6.374,25.4 -5.326,25.4 -4.126,25.4 -3.95,25.224 -3.95,24.056 -4.35,23.656 -4.35,23.651 -4.55,23.451 R27.1@-4.65,23.451
LED1C: D1.2 R31.1 U1.32 | length 10.3
  Top Layer w0.2: D1.2@-19.9,5.55 -20.05,5.7 -20.05,7.924 -19.674,8.3 -19.65,8.3 -19.65,8.648 -19.4,8.898 R31.1@-19.38,8.898 ; R31.1@-19.45,8.6 -19.25,8.8 -19.25,9.35 -18.482,10.118 -14.971,10.118 U1.32@-14.125,10.964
